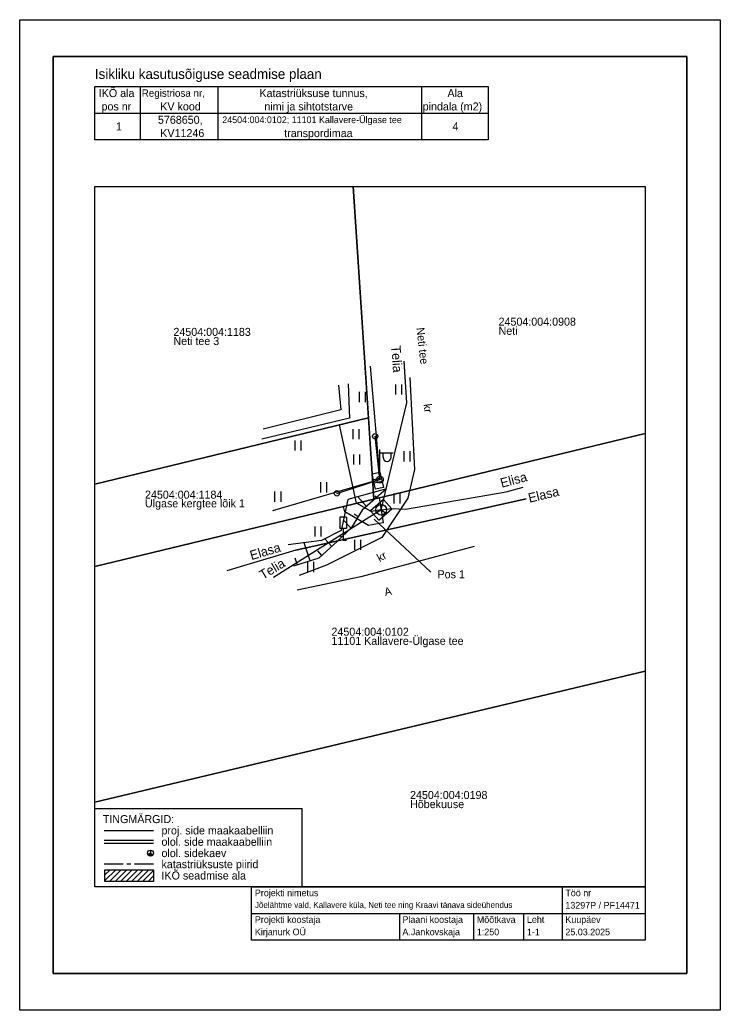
# Model space of a CAD drawing. Extents: x 558339.9 to 558392.4, y 6594202.6 to 6594276.8.
import ezdxf

# ---------------------------------------------------------------- set-up
doc = ezdxf.new("R2010")
doc.units = 0
for name, color, linetype in [('AED', 7, 'Continuous'), ('ELRAJATISMP', 7, 'Continuous'), ('HALJASTUS', 7, 'Continuous'), ('KASUTUSALA', 7, 'Continuous'), ('LIIKLUS', 7, 'Continuous'), ('MPOHULIIN', 7, 'Continuous'), ('PIIR', 7, 'Continuous'), ('POST', 7, 'Continuous'), ('PR_SIDE', 7, 'Continuous'), ('RELJEEF', 7, 'Continuous'), ('SIKAEV', 7, 'Continuous'), ('SITRASS', 7, 'Continuous'), ('TEE', 7, 'Continuous'), ('VORMISTUS', 7, 'Continuous')]:
    doc.layers.add(name, color=color, linetype=linetype)

msp = doc.modelspace()

# ---------------------------------------------------------------- linework, layer by layer
at = {"layer": 'AED'}
msp.add_lwpolyline([(558364.526, 6594249.515), (558364.64, 6594246.947), (558358.071, 6594245.359)], dxfattribs=at)
at = {"layer": 'ELRAJATISMP'}
for p, q in [((558367.014, 6594242.449), (558366.431, 6594242.32)), ((558367.072, 6594242.184), (558366.489, 6594242.055))]:
    msp.add_line(p, q, dxfattribs=at)
msp.add_lwpolyline([(558366.914, 6594242.9), (558367.172, 6594241.734), (558366.589, 6594241.605), (558366.331, 6594242.771)], close=True, dxfattribs=at)
at = {"layer": 'HALJASTUS'}
for p, q in [((558368.076, 6594249.466), (558368.076, 6594248.705)), ((558368.531, 6594249.466), (558368.531, 6594248.705)), ((558365.352, 6594248.907), (558365.352, 6594248.146)), ((558365.807, 6594248.907), (558365.807, 6594248.146)), ((558364.887, 6594246.112), (558364.887, 6594245.351)), ((558365.342, 6594246.112), (558365.342, 6594245.351)), ((558360.533, 6594245.273), (558360.533, 6594244.512)), ((558360.988, 6594245.273), (558360.988, 6594244.512)), ((558364.933, 6594244.225), (558364.933, 6594243.464)), ((558365.388, 6594244.225), (558365.388, 6594243.464)), ((558368.705, 6594244.458), (558368.705, 6594243.697)), ((558369.16, 6594244.458), (558369.16, 6594243.697)), ((558362.466, 6594242.128), (558362.466, 6594241.367)), ((558362.921, 6594242.128), (558362.921, 6594241.367)), ((558359.02, 6594241.43), (558359.02, 6594240.668)), ((558359.475, 6594241.43), (558359.475, 6594240.668)), ((558367.96, 6594241.29), (558367.96, 6594240.529)), ((558368.415, 6594241.29), (558368.415, 6594240.529)), ((558362.023, 6594238.821), (558362.023, 6594238.06)), ((558362.478, 6594238.821), (558362.478, 6594238.06)), ((558365.003, 6594237.819), (558365.003, 6594237.058)), ((558365.458, 6594237.819), (558365.458, 6594237.058)), ((558361.488, 6594236.165), (558361.488, 6594235.404)), ((558361.943, 6594236.165), (558361.943, 6594235.404))]:
    msp.add_line(p, q, dxfattribs=at)
msp.add_lwpolyline([(558363.805, 6594249.404), (558363.978, 6594247.553), (558358.165, 6594246.108)], dxfattribs=at)
at = {"layer": 'KASUTUSALA'}
msp.add_lwpolyline([(558367.169, 6594239.083), (558366.068, 6594238.901), (558364.276, 6594239.905), (558364.186, 6594240.323), (558366.45, 6594240.87), (558366.859, 6594240.969)], close=True, dxfattribs=at)
at = {"layer": 'LIIKLUS'}
for p, q in [((558363.904, 6594239.511), (558363.904, 6594238.661)), ((558364.404, 6594239.511), (558363.904, 6594239.511)), ((558364.404, 6594239.511), (558364.404, 6594238.661)), ((558364.404, 6594238.661), (558363.904, 6594238.661)), ((558364.154, 6594238.661), (558364.154, 6594237.761)), ((558364.404, 6594237.761), (558364.154, 6594237.761))]:
    msp.add_line(p, q, dxfattribs=at)
at = {"layer": 'MPOHULIIN'}
msp.add_lwpolyline([(558366.176, 6594250.834), (558366.919, 6594242.327), (558358.869, 6594239.994)], dxfattribs=at)
at = {"layer": 'PIIR'}
for p, q in [((558345.545, 6594218.138), (558386.795, 6594227.96)), ((558386.795, 6594227.96), (558345.545, 6594218.138))]:
    msp.add_line(p, q, dxfattribs=at)
for points in [[(558345.545, 6594241.994), (558366.05, 6594246.95), (558364.909, 6594264.303)], [(558364.909, 6594264.303), (558366.45, 6594240.87), (558386.795, 6594245.789)], [(558345.545, 6594235.817), (558366.45, 6594240.87), (558366.05, 6594246.95), (558345.545, 6594241.994)], [(558386.795, 6594245.789), (558366.45, 6594240.87), (558345.545, 6594235.817)]]:
    msp.add_lwpolyline(points, dxfattribs=at)
at = {"layer": 'POST'}
for p, q in [((558366.919, 6594242.577), (558366.919, 6594244.577)), ((558366.919, 6594244.327), (558367.919, 6594244.327)), ((558367.146, 6594244.006), (558367.146, 6594244.327)), ((558367.759, 6594244.006), (558367.759, 6594244.327)), ((558366.919, 6594242.327), (558366.919, 6594242.327))]:
    msp.add_line(p, q, dxfattribs=at)
msp.add_lwpolyline([(558363.686, 6594241.299), (558366.919, 6594242.327), (558366.557, 6594245.58)], dxfattribs=at)
for centre, radius in [((558366.557, 6594245.58), 0.2), ((558366.919, 6594242.327), 0.25), ((558366.919, 6594242.327), 0.0234), ((558363.686, 6594241.299), 0.2)]:
    msp.add_circle(centre, radius, dxfattribs=at)
msp.add_arc((558367.453, 6594244.006), 0.306, 180, 0, dxfattribs=at)
at = {"layer": 'PR_SIDE'}
msp.add_lwpolyline([(558367.006, 6594240.07), (558366.252, 6594239.946), (558365.159, 6594240.558), (558363.889, 6594246.428)], dxfattribs=at)
at = {"layer": 'RELJEEF'}
for p, q in [((558365.908, 6594240.317), (558365.259, 6594241.043)), ((558366.654, 6594240.983), (558366.546, 6594241.104)), ((558364.745, 6594238.707), (558364.174, 6594239.291)), ((558365.285, 6594239.547), (558364.974, 6594239.741)), ((558361.677, 6594236.231), (558361.241, 6594237.596)), ((558363.302, 6594237.323), (558362.779, 6594237.892)), ((558364.03, 6594238.008), (558363.915, 6594238.126)), ((558362.565, 6594236.647), (558362.258, 6594236.981)), ((558360.724, 6594235.927), (558360.561, 6594236.44))]:
    msp.add_line(p, q, dxfattribs=at)
for points in [[(558367.4, 6594241.649), (558364.504, 6594240.83), (558364.01, 6594238.527), (558362.531, 6594237.764), (558360.037, 6594237.439)], [(558367.4, 6594241.649), (558365.585, 6594240.029), (558364.785, 6594238.747), (558363.743, 6594237.728), (558362.345, 6594236.445), (558360.429, 6594235.833)]]:
    msp.add_lwpolyline(points, dxfattribs=at)
at = {"layer": 'SIKAEV'}
for p, q in [((558367.006, 6594240.07), (558366.674, 6594239.85)), ((558367.006, 6594240.47), (558367.006, 6594240.07)), ((558367.006, 6594240.07), (558367.338, 6594239.85))]:
    msp.add_line(p, q, dxfattribs=at)
msp.add_circle((558367.006, 6594240.07), 0.4, dxfattribs=at)
at = {"layer": 'SITRASS'}
msp.add_line((558367.006, 6594240.07), (558358.94, 6594234.997), dxfattribs=at)
for points in [[(558367.006, 6594240.07), (558368.935, 6594248.094), (558368.719, 6594251.216)], [(558367.006, 6594240.07), (558367.78, 6594240.157), (558368.827, 6594240.11), (558376.381, 6594241.427), (558377.654, 6594241.763)], [(558367.006, 6594240.07), (558367.78, 6594240.157), (558368.827, 6594240.11), (558376.381, 6594241.427), (558377.654, 6594241.763)], [(558377.884, 6594240.878), (558372.733, 6594239.732), (558360.622, 6594237.032), (558355.432, 6594235.499)], [(558360.622, 6594237.032), (558372.733, 6594239.732), (558377.884, 6594240.878)]]:
    msp.add_lwpolyline(points, dxfattribs=at)
msp.add_lwpolyline([(558366.823, 6594239.292), (558367.802, 6594240.147), (558367.19, 6594240.847), (558366.211, 6594239.992)], close=True, dxfattribs=at)
at = {"layer": 'TEE'}
for points in [[(558369.166, 6594249.998), (558369.504, 6594243.098), (558369.001, 6594240.944), (558367.067, 6594237.998), (558362.921, 6594235.905), (558360.849, 6594235.132)], [(558373.977, 6594237.306), (558365.48, 6594235.054), (558360.723, 6594234.047)]]:
    msp.add_lwpolyline(points, dxfattribs=at)
at = {"layer": 'VORMISTUS'}
for p, q in [((558348.932, 6594271.808), (558348.932, 6594267.808)), ((558354.757, 6594271.808), (558354.757, 6594267.808)), ((558370.032, 6594271.808), (558370.032, 6594267.808)), ((558345.532, 6594269.808), (558375.032, 6594269.808)), ((558366.49, 6594239.375), (558370.73, 6594235.384)), ((558346.246, 6594216.029), (558349.94, 6594216.029)), ((558346.246, 6594215.289), (558349.94, 6594215.289)), ((558346.246, 6594215.068), (558349.94, 6594215.068)), ((558349.715, 6594214.554), (558349.715, 6594214.329)), ((558349.715, 6594214.329), (558349.528, 6594214.205)), ((558349.715, 6594214.329), (558349.902, 6594214.205)), ((558347.656, 6594213.5), (558346.245, 6594213.5)), ((558347.109, 6594213.087), (558346.299, 6594212.277)), ((558346.697, 6594213.087), (558346.299, 6594212.689)), ((558347.521, 6594213.087), (558346.647, 6594212.213)), ((558347.933, 6594213.087), (558347.059, 6594212.213)), ((558348.345, 6594213.087), (558347.471, 6594212.213)), ((558348.756, 6594213.087), (558347.883, 6594212.213)), ((558348.238, 6594213.5), (558347.947, 6594213.5)), ((558349.168, 6594213.087), (558348.295, 6594212.213)), ((558349.94, 6594213.5), (558348.529, 6594213.5)), ((558349.58, 6594213.087), (558348.706, 6594212.213)), ((558349.94, 6594213.035), (558349.118, 6594212.213)), ((558349.94, 6594212.623), (558349.53, 6594212.213)), ((558380.568, 6594211.803), (558380.568, 6594209.803)), ((558357.295, 6594209.803), (558386.795, 6594209.803)), ((558368.389, 6594209.803), (558368.389, 6594207.803)), ((558373.932, 6594209.803), (558373.932, 6594207.803)), ((558377.684, 6594209.803), (558377.684, 6594207.803)), ((558380.568, 6594209.803), (558380.568, 6594207.803))]:
    msp.add_line(p, q, dxfattribs=at)
for points in [[(558339.92, 6594276.803), (558392.42, 6594276.803), (558392.42, 6594202.553), (558339.92, 6594202.553)], [(558342.42, 6594205.303), (558389.92, 6594205.303), (558389.92, 6594274.053), (558342.42, 6594274.053)], [(558342.42, 6594274.053), (558389.92, 6594274.053), (558389.92, 6594205.303), (558342.42, 6594205.303)], [(558345.532, 6594271.808), (558375.032, 6594271.808), (558375.032, 6594267.808), (558345.532, 6594267.808)], [(558386.795, 6594211.803), (558345.545, 6594211.803), (558345.545, 6594264.303), (558386.795, 6594264.303)], [(558345.54, 6594211.8), (558345.54, 6594217.662), (558361.07, 6594217.662), (558361.07, 6594211.8)], [(558346.299, 6594213.087), (558349.94, 6594213.087), (558349.94, 6594212.213), (558346.299, 6594212.213)], [(558357.295, 6594211.803), (558386.795, 6594211.803), (558386.795, 6594207.803), (558357.295, 6594207.803)]]:
    msp.add_lwpolyline(points, close=True, dxfattribs=at)
msp.add_circle((558349.715, 6594214.329), 0.225, dxfattribs=at)
for radius in [0.214, 0.203, 0.191, 0.18, 0.169, 0.158, 0.146, 0.135, 0.124, 0.113, 0.101, 0.0901, 0.0788, 0.0676, 0.0563, 0.0451, 0.0338, 0.0225]:
    msp.add_arc((558349.715, 6594214.329), radius, 213.53047, 326.46953, dxfattribs=at)

# ---------------------------------------------------------------- texts
at = {"layer": 'PIIR'}
for s, p in [('24504:004:0908', (558375.807, 6594253.873)), ('24504:004:1183', (558351.434, 6594253.107)), ('Neti', (558375.807, 6594253.186)), ('Neti tee 3', (558351.434, 6594252.421)), ('24504:004:1184', (558349.303, 6594240.901)), ('Ülgase kergtee lõik 1', (558349.303, 6594240.251)), ('24504:004:0102', (558363.281, 6594230.627)), ('11101 Kallavere-Ülgase tee', (558363.281, 6594229.94)), ('24504:004:0198', (558369.172, 6594218.388)), ('Hõbekuuse', (558369.172, 6594217.702))]:
    msp.add_text(s, height=0.6, dxfattribs=at).set_placement(p)
at = {"layer": 'SITRASS'}
for s, rotation, p in [('Telia', 273.91186, (558367.761, 6594252.361)), ('Elisa', 14.73869, (558376.045, 6594241.716)), ('Elasa', 13.49304, (558378.125, 6594240.593)), ('Elasa', 16.41351, (558357.29, 6594236.291)), ('Telia', 30.94053, (558358.144, 6594234.816))]:
    msp.add_text(s, height=0.7, rotation=rotation, dxfattribs=at).set_placement(p)
at = {"layer": 'TEE'}
for s, rotation, p in [('Neti tee', 276.46097, (558369.648, 6594253.702)), ('kr', 277.16046, (558370.173, 6594247.976)), ('kr', 28.60638, (558366.894, 6594236.14)), ('A', 13.81045, (558367.322, 6594233.591))]:
    msp.add_text(s, height=0.6, rotation=rotation, dxfattribs=at).set_placement(p)
at = {"layer": 'VORMISTUS'}
for s, height, p in [('Isikliku kasutusõiguse seadmise plaan', 0.75, (558345.548, 6594272.37)), ('IKÕ ala', 0.6, (558345.837, 6594271.008)), ('Registriosa nr,', 0.55, (558349.058, 6594271.033)), ('Katastriüksuse tunnus,', 0.6, (558357.885, 6594271.008)), ('Ala', 0.6, (558371.977, 6594271.008)), ('pos nr', 0.6, (558346.047, 6594270.008)), ('KV kood', 0.6, (558350.449, 6594270.008)), ('nimi ja sihtotstarve', 0.6, (558358.254, 6594270.008)), ('pindala (m2)', 0.6, (558370.12, 6594270.008)), ('5768650,', 0.6, (558350.275, 6594269.008)), ('24504:004:0102; 11101 Kallavere-Ülgase tee', 0.5, (558355.094, 6594269.058)), ('1', 0.6, (558347.127, 6594268.508)), ('4', 0.6, (558372.352, 6594268.508)), ('KV11246', 0.6, (558350.449, 6594268.008)), ('transpordimaa', 0.6, (558359.739, 6594268.008)), ('Pos 1', 0.6, (558371.23, 6594234.934)), ('TINGMÄRGID:', 0.6, (558346.14, 6594216.579)), ('proj. side maakaabelliin', 0.6, (558350.54, 6594215.729)), ('olol. side maakaabelliin', 0.6, (558350.54, 6594214.879)), ('olol. sidekaev', 0.6, (558350.54, 6594214.029)), ('katastriüksuste piirid', 0.6, (558350.54, 6594213.2)), ('IKÕ seadmise ala', 0.6, (558350.54, 6594212.35)), ('Projekti nimetus', 0.5, (558357.544, 6594211.099)), ('Töö nr', 0.5, (558380.817, 6594211.099)), ('Jõelähtme vald, Kallavere küla, Neti tee ning Kraavi tänava sideühendus', 0.45, (558357.544, 6594210.22)), ('13297P / PF14471', 0.5, (558380.817, 6594210.17)), ('Projekti koostaja', 0.5, (558357.544, 6594209.099)), ('Plaani koostaja', 0.5, (558368.602, 6594209.099)), ('Mõõtkava', 0.5, (558374.181, 6594209.099)), ('Leht', 0.5, (558377.933, 6594209.099)), ('Kuupäev', 0.5, (558380.817, 6594209.099)), ('Kirjanurk OÜ', 0.5, (558357.544, 6594208.17)), ('A.Jankovskaja', 0.5, (558368.602, 6594208.17)), ('1:250', 0.5, (558374.181, 6594208.17)), ('1-1', 0.5, (558377.933, 6594208.17)), ('25.03.2025', 0.5, (558380.817, 6594208.17))]:
    msp.add_text(s, height=height, dxfattribs=at).set_placement(p)

doc.saveas('drawing.dxf')
